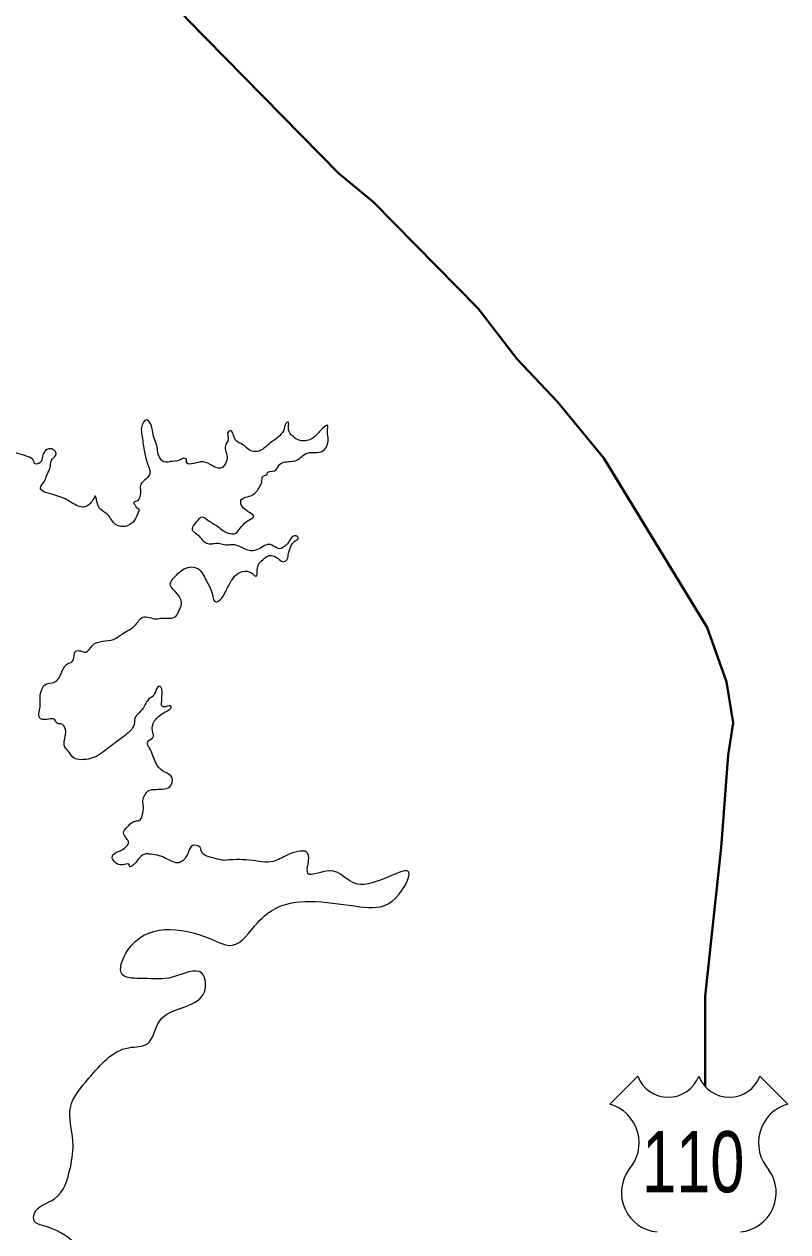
# Model space of a CAD drawing. Extents: x 553962 to 842807, y 8883888 to 9032388.
# Drawn here: x 579563 to 583934, y 8979171 to 8986079 of the extents above; entities that cross this region are included whole.
import ezdxf
from ezdxf.enums import TextEntityAlignment as Align

# ---------------------------------------------------------------- set-up
doc = ezdxf.new("R2010")
doc.units = 0
doc.header["$LTSCALE"] = 20
for name, color, linetype, lineweight in [('12', 7, 'Continuous', 25), ('25', 7, 'Continuous', 13), ('48', 7, 'Continuous', 25)]:
    doc.layers.add(name, color=color, linetype=linetype, lineweight=lineweight)

msp = doc.modelspace()

# ---------------------------------------------------------------- linework, layer by layer
at = {"layer": '12', "lineweight": 40}
msp.add_lwpolyline([(577759.92, 8988875.79), (577832.52, 8988674.72), (577901.46, 8988571.1), (578184.7, 8988310.33), (578513.4, 8987946.16), (578671.18, 8987814.27), (579419.18, 8987100.9), (579808.09, 8986794.1), (580282.98, 8986357.3), (580496.32, 8986108.01), (581364.79, 8985224.5), (581561.26, 8985062.54), (582162.45, 8984452.73), (582384.65, 8984161.89), (582616.43, 8983918.76), (582880.15, 8983596.66), (583472.38, 8982628.41), (583582.53, 8982317.65), (583621.66, 8982083.18), (583591.56, 8981897.76), (583552.47, 8981370.04), (583461.67, 8980518.06), (583461.67, 8980001.2)], dxfattribs=at)
at = {"layer": '25'}
for points in [[(579970.29, 8983381.66), (579928.31, 8983326.21), (579913.32, 8983318.62), (579880.62, 8983319.78), (579816.04, 8983353.54), (579732.63, 8983385.98), (579656.63, 8983427.24), (579677.54, 8983461.25), (579700.67, 8983516.64), (579706.8, 8983527.97), (579715.1, 8983564.46), (579723.54, 8983590.89), (579746.99, 8983622.39), (579727.81, 8983646.22), (579713.93, 8983649.95), (579678.97, 8983632.25), (579647.2, 8983565.52), (579623.29, 8983566.7), (579619.37, 8983578.01), (579581.26, 8983606.81), (579528.24, 8983623), (579513.1, 8983626.72), (579471.48, 8983636.66), (579433.37, 8983665.46), (579440.41, 8983701.94), (579442.44, 8983737.15), (579441.15, 8983739.67), (579447.04, 8983768.6), (579413, 8983867.82), (579391.28, 8983892.9), (579318.54, 8983971.9), (579294.19, 8984005.77), (579301.24, 8984042.25), (579315.84, 8984077.5), (579342.98, 8984115.3), (579355.31, 8984132.94), (579360.2, 8984143.01)], [(580290.32, 8983788.71), (580262.29, 8983816.28), (580235.24, 8983772.2), (580237.08, 8983729.46), (580249.58, 8983642.74), (580269.5, 8983564.85), (580280.42, 8983502.02), (580228.5, 8983437.74), (580228.86, 8983411.34), (580225.55, 8983377.38), (580205.82, 8983349.67), (580190.82, 8983343.34), (580198.59, 8983327.01), (580199.89, 8983323.25), (580212.65, 8983309.45), (580216.44, 8983308.21), (580211.86, 8983275.51), (580188.56, 8983232.69), (580142.41, 8983206.15), (580080.59, 8983222.31), (580035.81, 8983278.75), (579995.17, 8983308.81), (579980.86, 8983343.97), (579975.53, 8983366.58), (579970.29, 8983381.66)], [(581134.02, 8983136.17), (581123.84, 8983150.55), (581105.56, 8983150.55), (581070.32, 8983105.81), (581052.91, 8983091.93), (581034.22, 8983079.3), (580963.5, 8983102.98), (580932.22, 8983091.57), (580892.27, 8983071.33), (580850.84, 8983067.44), (580790.13, 8983093.66), (580748.55, 8983101.08), (580717.15, 8983098.47), (580683.09, 8983107.17), (580642.88, 8983105.8), (580622.78, 8983104.48), (580594.97, 8983115.71), (580573.22, 8983143.31), (580544, 8983165.85), (580526.11, 8983187.17), (580550.65, 8983231.25), (580582.92, 8983261.52), (580614.62, 8983241.5), (580670.42, 8983206.46), (580700.91, 8983182.66), (580728.78, 8983167.66), (580775.29, 8983167.79), (580800.05, 8983195.53), (580833.5, 8983232.09), (580860.93, 8983248.51), (580877.07, 8983263.65), (580868.11, 8983274.94), (580826.23, 8983303.73), (580804.43, 8983335.1), (580804.17, 8983353.96), (580830.31, 8983372.89), (580870.37, 8983385.59), (580911.22, 8983432.23), (580924.55, 8983468.73), (580931.74, 8983493.89), (580954.2, 8983506.53), (580954.18, 8983507.79), (580996.7, 8983524.26), (581025.12, 8983560.81), (581056.35, 8983574.73), (581131.59, 8983588.78), (581158.94, 8983611.49), (581195.17, 8983627.95), (581227.86, 8983628.04), (581272.97, 8983638.23), (581301.27, 8983683.58), (581303.51, 8983703.7), (581299.12, 8983748.95), (581299.89, 8983784.16), (581260.77, 8983755.98), (581236.52, 8983729.91), (581217.9, 8983712.25), (581141.41, 8983698.19), (581085.54, 8983738.26), (581076.28, 8983772.18), (581072.08, 8983803.6), (581068.32, 8983802.33), (581051.26, 8983763.3), (581027.87, 8983726.77), (580969.41, 8983681.34), (580898.39, 8983634.61), (580856.82, 8983640.77), (580813.61, 8983674.59), (580774.3, 8983699.62), (580739.63, 8983752.32), (580732.14, 8983748.53), (580731.55, 8983699.49), (580718.05, 8983675.56), (580716, 8983641.61), (580725.3, 8983605.18), (580720.64, 8983578.76), (580689.74, 8983539.69), (580627.85, 8983560.88), (580572.35, 8983574.55), (580493.15, 8983574.31), (580490.39, 8983591.91), (580477.77, 8983595.64), (580476.51, 8983595.64), (580454.02, 8983585.51), (580401.34, 8983576.56), (580373.74, 8983572.7), (580343.29, 8983592.73), (580322.13, 8983669.36), (580307.73, 8983710.81), (580297.07, 8983754.78), (580290.32, 8983788.71)], [(579888.16, 8982493.78), (579915.92, 8982486.32), (579954.35, 8982525.41), (580074.57, 8982559.71), (580129.7, 8982593.98), (580199.18, 8982640.54), (580243.82, 8982685.94), (580319.37, 8982677.36), (580352, 8982681.23), (580431.06, 8982691.52), (580449.49, 8982723.01), (580464.06, 8982760.77), (580459.92, 8982787.16), (580418.94, 8982842.36), (580399.6, 8982877.51), (580413.08, 8982902.69), (580435.37, 8982927.9), (580511.43, 8982973.39), (580556.81, 8982964.73), (580606.8, 8982894.47), (580640.55, 8982816.62), (580659.99, 8982773.93), (580678.75, 8982781.53), (580720.66, 8982842), (580753.8, 8982901.19), (580786, 8982936.49), (580839.88, 8982949.22), (580880.4, 8982927.97), (580889.31, 8982920.45), (580898.73, 8982967), (580930.72, 8983017.38), (580964.37, 8983038.86), (581023.77, 8983016.4), (581049.08, 8983003.91), (581064.06, 8983011.49), (581074.96, 8983041.7), (581112.83, 8983122.28), (581134.02, 8983136.17)], [(580701.6, 8981295.5), (580609.49, 8981320.37), (580584.14, 8981335.38), (580569.85, 8981369.29), (580528.21, 8981380.48), (580503.56, 8981343.94), (580472.81, 8981294.82), (580447.84, 8981282.17), (580415.08, 8981287.1), (580366.99, 8981310.85), (580278.7, 8981331.96), (580253.55, 8981331.89), (580216.25, 8981301.6), (580198.96, 8981278.92), (580166.5, 8981262.48), (580166.42, 8981268.76), (580124.91, 8981269.9), (580087.03, 8981282.36), (580067.81, 8981308.7), (580071.34, 8981326.32), (580116.25, 8981351.59), (580143.63, 8981371.79), (580160.92, 8981394.47), (580132.48, 8981452.22), (580152.14, 8981484.97), (580191.92, 8981517.78), (580211.98, 8981521.61), (580220.77, 8981522.89), (580239.21, 8981553.12), (580246.08, 8981602.18), (580243.09, 8981637.37), (580255.19, 8981671.35), (580273.76, 8981692.78), (580318.89, 8981701.72), (580355.33, 8981703.08), (580396.64, 8981715.78), (580411.02, 8981767.37), (580357.69, 8981806.19), (580318.1, 8981851.33), (580280.46, 8981937.97), (580268.78, 8981964.34), (580279.84, 8981983.23), (580304.65, 8982007.19), (580300.66, 8982023.53), (580301.16, 8982078.85), (580346.98, 8982129.27), (580379.39, 8982149.49), (580399.33, 8982162.12), (580405.41, 8982177.22), (580371.51, 8982174.61), (580352.61, 8982177.07), (580350.96, 8982205.98), (580351.84, 8982233.64), (580344.83, 8982286.43), (580341.01, 8982290.19), (580305.21, 8982242.3), (580266.72, 8982206.99), (580252.01, 8982179.28), (580221.12, 8982140.22), (580196.42, 8982107.45), (580194.29, 8982079.79), (580170.99, 8982036.97), (580122.51, 8981996.59), (580061.55, 8981949.89), (580021.73, 8981919.6), (579976.87, 8981890.55), (579931.82, 8981875.33), (579877.8, 8981872.65), (579841.16, 8981886.38), (579814.26, 8981922.76), (579804.06, 8981932.78), (579792.44, 8981955.38), (579798.09, 8982001.92), (579794.82, 8982057.23), (579778.23, 8982074.78), (579751.76, 8982079.73), (579738.94, 8982098.55), (579674.79, 8982100.88), (579653.3, 8982109.61), (579649.03, 8982146.06), (579653.83, 8982162.42), (579654.35, 8982216.48), (579689.62, 8982303.34), (579732.22, 8982313.53), (579754.64, 8982328.68), (579781.61, 8982379.05), (579817.46, 8982423.16), (579832.48, 8982428.23), (579848.48, 8982453.43), (579859.26, 8982492.43), (579888.16, 8982493.78)], [(581113.25, 8977420.58), (581052.03, 8977586.83), (581044.43, 8977700.97), (581112.87, 8977822.71), (581219.32, 8977944.45), (581226.93, 8977959.67), (581325.78, 8977997.71), (581150.89, 8978172.72), (581059.64, 8978180.33), (580846.72, 8978073.8), (580823.91, 8977997.71), (580687.04, 8978020.54), (580474.13, 8978324.9), (580542.56, 8978644.47), (580633.81, 8978751), (580808.7, 8978933.61), (580808.7, 8978941.22), (580763.08, 8978956.44), (580603.4, 8978887.96), (580382.88, 8978773.82), (580109.13, 8978811.87), (579858.2, 8979101), (579668.1, 8979207.53), (579622.47, 8979230.36), (579622.47, 8979276.01), (579736.54, 8979359.71), (579827.77, 8979539.3), (579842.98, 8979691.48), (579827.77, 8979881.7), (579934.22, 8980049.1), (580162.35, 8980224.1), (580268.8, 8980246.93), (580337.24, 8980376.28), (580489.32, 8980459.98), (580595.78, 8980543.68), (580580.57, 8980650.2), (580413.28, 8980627.37), (580245.99, 8980619.76), (580124.32, 8980642.59), (580154.74, 8980779.55), (580626.19, 8980848.03), (580755.46, 8980809.99), (580899.94, 8980939.34), (581006.39, 8981023.04), (581485.45, 8981030.64), (581667.94, 8981061.08), (581765.27, 8981228.48), (581468.72, 8981160), (581309.03, 8981236.08), (581187.37, 8981220.87), (581187.37, 8981335), (581073.31, 8981327.39), (580989.66, 8981289.35), (580852.79, 8981296.96), (580701.6, 8981295.5)]]:
    msp.add_spline(points, degree=3, dxfattribs=at)
at = {"layer": '48'}
for p, q in [((582914.86, 8979901.27), (583074.79, 8980061.17)), ((583774.11, 8980061.17), (583934.06, 8979901.27))]:
    msp.add_line(p, q, dxfattribs=at)
for centre, radius, start, end in [((583249.62, 8980128.14), 187.21, 200.95927, 339.04073), ((583599.27, 8980128.14), 187.21, 200.95927, 339.04073), ((582852.78, 8979679.41), 230.34, 317.5721, 74.36886), ((583996.1, 8979679.41), 230.34, 105.62774, 222.4279), ((583206.28, 8979394.27), 224.71, 144.73733, 264.65778), ((583642.61, 8979394.27), 224.71, 275.34222, 35.26267)]:
    msp.add_arc(centre, radius, start, end, dxfattribs=at)

# ---------------------------------------------------------------- texts
at = {"layer": '48', "width": 0.75}
msp.add_text('110', height=350, dxfattribs=at).set_placement((583392.51, 8979396.64), align=Align.CENTER)

doc.saveas('drawing.dxf')
